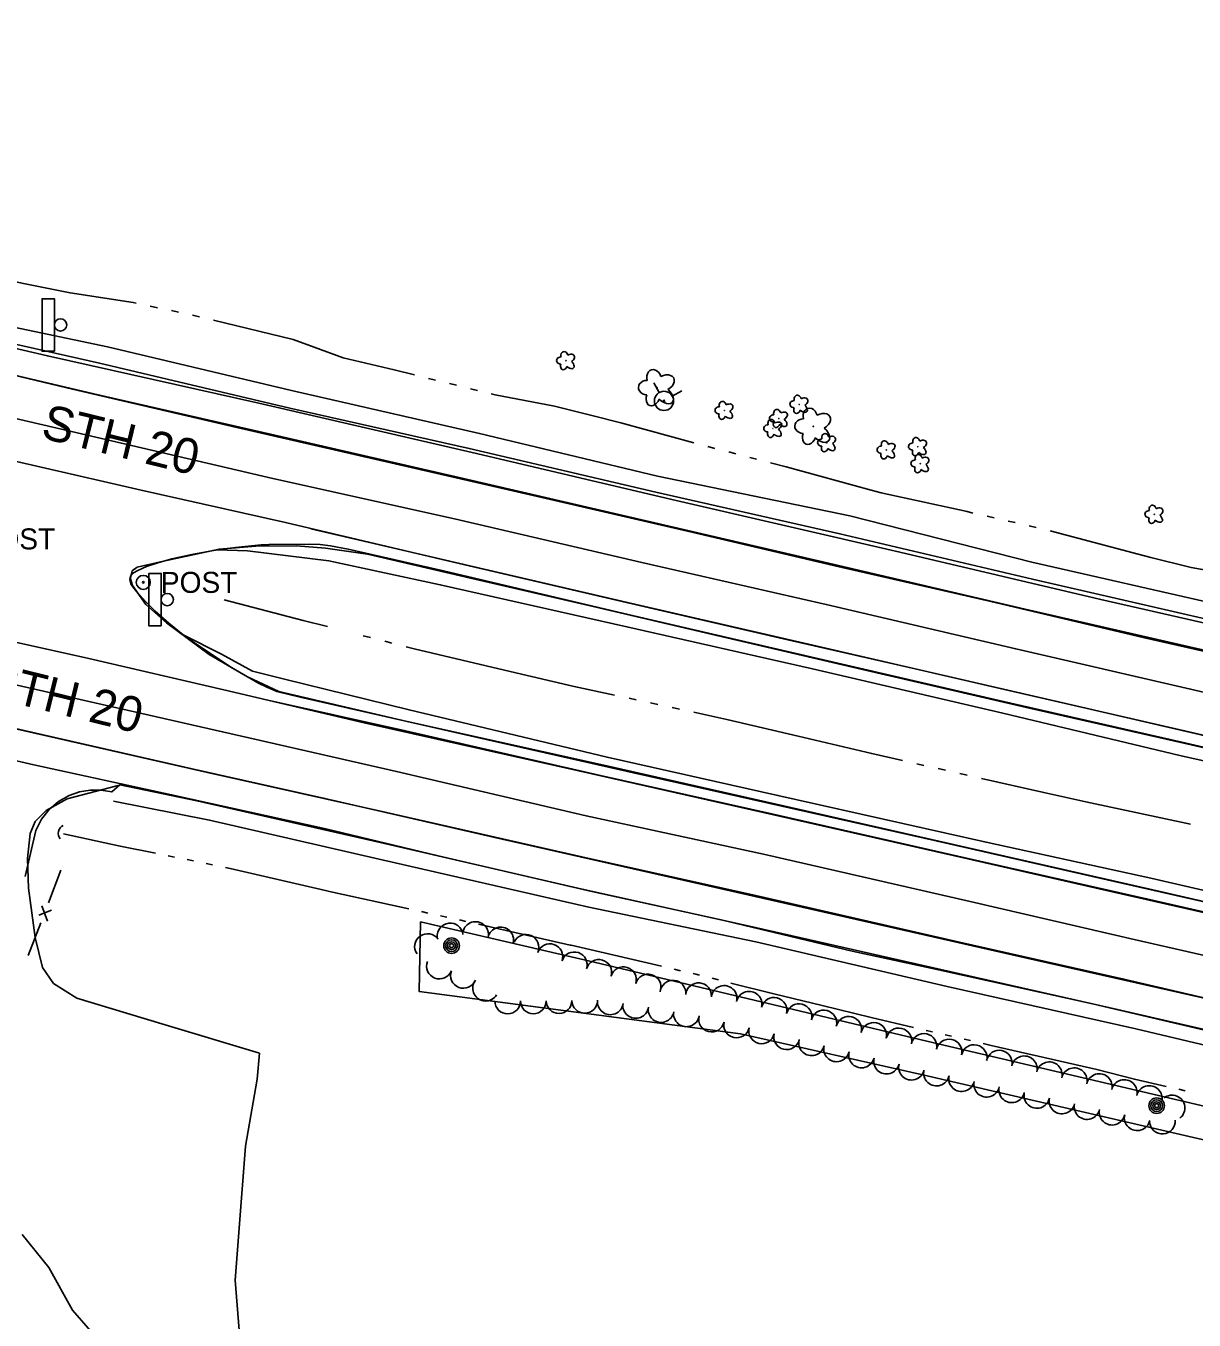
# Model space of a CAD drawing. Extents: x 588843 to 2552415, y 180129 to 269402.
# Drawn here: x 597218.6 to 597551.8, y 184038.8 to 184408.2 of the extents above; entities that cross this region are included whole.
import ezdxf

# ---------------------------------------------------------------- set-up
doc = ezdxf.new("R2010")
doc.units = 0
for name, color, linetype in [('Default', 7, 'Continuous'), ('E_DRN', 7, 'Continuous'), ('E_DWY', 7, 'Continuous'), ('E_FEN_P', 7, 'Continuous'), ('E_LAND_BrushLine', 7, 'Continuous'), ('E_LAND_TreeLine_P', 7, 'Continuous'), ('E_LAND_Vegetation', 7, 'Continuous'), ('E_MISCPROP', 7, 'Continuous'), ('E_RDWY', 7, 'Continuous'), ('E_RDWY_AsphConc', 7, 'Continuous'), ('E_RDWY_Gravel', 7, 'Continuous'), ('E_RDWY_PavtEdge', 7, 'Continuous'), ('E_RDWY_Text', 7, 'Continuous'), ('E_SGN', 7, 'Continuous'), ('E_UTL_WHydrant', 7, 'Continuous'), ('E_WTR_P', 7, 'Continuous')]:
    doc.layers.add(name, color=color, linetype=linetype)

# ---------------------------------------------------------------- blocks, each defined once
blk = doc.blocks.new('BUSH_1')
at = {"layer": 'Default'}
blk.add_circle((0, 0), 0.0916, dxfattribs=at)
for centre, major_axis, ratio in [((-2.84, 0.08), (2.47, -0.06), 0.832022), ((-0.84, 2.66), (0.68, -2.49), 0.782863), ((2.12, 1.37), (-2.64, -1.46), 0.691916), ((-1.15, -2.62), (0.9, 2.43), 0.716896), ((1.86, -1.85), (-2.51, 2.29), 0.560249)]:
    blk.add_ellipse(centre, major_axis=major_axis, ratio=ratio, start_param=1.570796, end_param=4.712389, dxfattribs=at)
blk = doc.blocks.new('DTRE_1_1')
at = {"layer": 'Default'}
blk.add_circle((-0.18, 0), 0.183, dxfattribs=at)
for centre, major_axis, ratio in [((-1.87, 5.32), (1.36, -4.98), 0.782863), ((4.06, 2.74), (-5.27, -2.93), 0.691916), ((-5.87, 0.15), (4.93, -0.12), 0.832022), ((-2.49, -5.24), (1.8, 4.86), 0.716896), ((3.54, -3.71), (-5.01, 4.58), 0.560249)]:
    blk.add_ellipse(centre, major_axis=major_axis, ratio=ratio, start_param=1.570796, end_param=4.712389, dxfattribs=at)
blk = doc.blocks.new('SGN_1')
at = {"layer": 'Default'}
blk.add_lwpolyline([(-3.5, -15), (-10.5, -15), (-10.5, 15), (-3.5, 15)], close=True, dxfattribs=at)
blk.add_circle((0, 0), 3.5, dxfattribs=at)
blk = doc.blocks.new('POST_1')
at = {"layer": 'Default'}
for radius in [4, 0.5]:
    blk.add_circle((0, 0), radius, dxfattribs=at)
blk.add_text('POST', height=12, dxfattribs=at).set_placement((10, -6))
blk = doc.blocks.new('CULV2_4')
at = {"layer": 'E_DRN'}
blk.add_arc((65, 48), 80.7, 216.8699, 323.1301, dxfattribs=at)
blk = doc.blocks.new('HYD_3')
at = {"layer": 'E_UTL_WHydrant'}
for p, q in [((-12.6, 12.6), (-27.3, 27.3)), ((12.6, 12.6), (27.3, 27.3))]:
    blk.add_line(p, q, dxfattribs=at)
for radius in [18, 1.38]:
    blk.add_circle((0, 0), radius, dxfattribs=at)
blk = doc.blocks.new('POLE_3')
at = {"layer": 'E_MISCPROP'}
for radius in [14.6, 11, 7.32, 3.66]:
    blk.add_circle((0, 0), radius, dxfattribs=at)

msp = doc.modelspace()

# ---------------------------------------------------------------- linework, layer by layer
at = {"layer": 'E_DWY'}
for points in [[(597246.35, 184191.76), (597230.31, 184187.57), (597224.35, 184184.27), (597221.18, 184181.15), (597219.79, 184177.65), (597219, 184170.61), (597219.28, 184162.12), (597221.17, 184148.04), (597223.32, 184139.46), (597226.47, 184134.91), (597233.08, 184130.66), (597257.36, 184123.42), (597285.2, 184114.99)], [(597289.65, 183941.21), (597283.81, 184004.99), (597279.81, 184031.22), (597278.24, 184050.27), (597279.4, 184065.09), (597281.23, 184088.44), (597284.53, 184107.61), (597285.2, 184114.99)], [(597217.5, 184063.27), (597225.08, 184053.82), (597231.81, 184041.65), (597240.21, 184032.08), (597248.96, 184023.04), (597253.27, 184015.43), (597252.98, 184008.68), (597247.63, 183979.46), (597243.29, 183967.94), (597236.18, 183952.88), (597231.24, 183945.62), (597225.75, 183938.73), (597219.12, 183923.11), (597199.9, 183923.64)]]:
    msp.add_lwpolyline(points, dxfattribs=at)
at = {"layer": 'E_FEN_P'}
for p, q in [((597225.89, 184155.79), (597222.21, 184154.41)), ((597223.14, 184157.01), (597224.71, 184152.7))]:
    msp.add_line(p, q, dxfattribs=at)
for points in [[(597228.54, 184167.21), (597224.98, 184157.94)], [(597222.79, 184152.2), (597219.24, 184142.93)]]:
    msp.add_lwpolyline(points, dxfattribs=at)
at = {"layer": 'E_LAND_BrushLine'}
for points in [[(597331.09, 184152.51), (597330.77, 184132.6), (597422.37, 184120.57), (597474.79, 184108.77), (597638.69, 184070.76), (597746.75, 184045.7), (597747.75, 184054.95)], [(597747.75, 184054.95), (597638.57, 184080.18), (597475.59, 184118.48), (597380.66, 184140.96), (597331.09, 184152.51)]]:
    msp.add_lwpolyline(points, dxfattribs=at)
at = {"layer": 'E_LAND_TreeLine_P'}
for centre, start, end in [((597339.57, 184148.47), 6.3494, 186.3494), ((597346.83, 184148.87), 347.7278, 167.7278), ((597333.13, 184145.42), 35.0756, 215.0756), ((597354, 184147.31), 347.7278, 167.7278), ((597361.22, 184145.22), 336.4179, 156.4179), ((597368.03, 184142.54), 341.5352, 161.5352), ((597374.99, 184140.22), 341.5352, 161.5352), ((597336.52, 184139.86), 158.7217, 338.7217), ((597381.99, 184138.05), 343.5064, 163.5064), ((597343.35, 184137.2), 158.7217, 338.7217), ((597389.02, 184135.97), 343.5064, 163.5064), ((597396.05, 184133.89), 343.5064, 163.5064), ((597349.69, 184133.56), 148.0436, 328.0436), ((597403.14, 184132.13), 354.556, 174.556), ((597410.44, 184131.43), 354.556, 174.556), ((597417.72, 184130.64), 346.7938, 166.7938), ((597424.86, 184128.97), 346.7938, 166.7938), ((597355.98, 184129.9), 180.3505, 0.3505), ((597363.31, 184129.94), 180.3505, 0.3505), ((597370.64, 184130), 180.6216, 0.6216), ((597377.97, 184130.08), 180.6216, 0.6216), ((597385.27, 184129.66), 171.9341, 351.9341), ((597392.53, 184128.63), 171.9341, 351.9341), ((597431.98, 184127.23), 345.7934, 165.7934), ((597439.09, 184125.43), 345.7934, 165.7934), ((597399.76, 184127.46), 170.4254, 350.4254), ((597406.99, 184126.24), 170.4254, 350.4254), ((597414.16, 184124.73), 166.8205, 346.8205), ((597446.2, 184123.63), 345.7934, 165.7934), ((597453.3, 184121.83), 345.7934, 165.7934), ((597421.3, 184123.06), 166.8205, 346.8205), ((597428.44, 184121.39), 166.8205, 346.8205), ((597460.42, 184120.08), 347.5295, 167.5295), ((597467.58, 184118.5), 347.5295, 167.5295), ((597435.58, 184119.71), 166.8205, 346.8205), ((597442.7, 184117.99), 166.2327, 346.2327), ((597474.74, 184116.92), 347.5295, 167.5295), ((597481.9, 184115.33), 347.5295, 167.5295), ((597449.82, 184116.24), 166.2327, 346.2327), ((597456.94, 184114.5), 166.2327, 346.2327), ((597489.06, 184113.75), 347.5295, 167.5295), ((597496.21, 184112.17), 347.5295, 167.5295), ((597503.37, 184110.55), 346.6039, 166.6039), ((597464.07, 184112.75), 166.2327, 346.2327), ((597471.19, 184111.01), 166.2327, 346.2327), ((597510.5, 184108.85), 346.6039, 166.6039), ((597517.63, 184107.15), 346.6039, 166.6039), ((597478.32, 184109.34), 167.449, 347.449), ((597485.48, 184107.74), 167.449, 347.449), ((597492.64, 184106.15), 167.449, 347.449), ((597524.76, 184105.46), 346.6039, 166.6039), ((597531.89, 184103.76), 346.6039, 166.6039), ((597499.79, 184104.56), 167.449, 347.449), ((597506.95, 184102.96), 167.449, 347.449), ((597539.02, 184102.06), 346.6039, 166.6039), ((597545.51, 184099.35), 308.2942, 128.2942), ((597514.11, 184101.37), 167.449, 347.449), ((597521.26, 184099.78), 167.449, 347.449), ((597528.42, 184098.18), 167.449, 347.449), ((597535.57, 184096.59), 167.449, 347.449), ((597542.78, 184095.63), 183.8381, 3.8381)]:
    msp.add_arc(centre, 3.67, start, end, dxfattribs=at)
at = {"layer": 'E_RDWY'}
for points in [[(596831.75, 184400.44), (596858.75, 184393.38), (596892.45, 184384.48), (596919.43, 184377.87), (596951.34, 184370.1), (596983.45, 184362.27), (597016.79, 184354.74), (597046.68, 184347.63), (597079.81, 184340.05), (597123.33, 184329.81), (597158.41, 184321.69), (597191.53, 184314.11), (597231.88, 184304.53), (597278.69, 184293.59), (597318.11, 184284.48), (597364.49, 184273.87), (597407.26, 184263.94), (597449.32, 184254.1), (597493.42, 184244.01), (597537.64, 184233.58), (597587.58, 184222.19), (597639.5, 184210.36), (597689.48, 184198.75)], [(596815.1, 184380.55), (596855.37, 184370.13), (596904.64, 184357.46), (596969.32, 184341.58), (597021.23, 184329.33), (597056.25, 184321.02), (597109.12, 184308.82), (597158.76, 184297.1), (597205.08, 184286.29), (597251.45, 184275.68), (597292.62, 184266.4), (597342.16, 184254.71), (597389.87, 184243.62), (597437.19, 184232.64), (597472.2, 184224.65), (597520.55, 184213.6), (597569.33, 184202.21), (597631.03, 184188.1), (597685.98, 184175.44)], [(596807.31, 184329.2), (596842.23, 184319.94), (596876.16, 184311.09), (596912.83, 184301.9), (596945.36, 184294.06), (596984.2, 184285.11), (597027.27, 184275.1), (597066.2, 184266.12), (597109.25, 184256.43), (597150.88, 184246.92), (597194.98, 184236.83), (597236.5, 184227.67), (597275.02, 184218.71), (597315.1, 184209.31), (597376.66, 184195.45), (597431.4, 184183.15), (597485.2, 184170.91), (597526.83, 184161.4), (597571.25, 184151.33), (597617.09, 184141.08), (597657, 184131.83), (597684.02, 184125.73)], [(596813.68, 184302.57), (596852.3, 184292.45), (596895.32, 184281.51), (596939.25, 184270.83), (596989.1, 184259.47), (597040.33, 184247.83), (597085.56, 184237.65), (597127.55, 184227.93), (597167.69, 184218.73), (597214.72, 184207.83), (597265.96, 184196.19), (597303.87, 184187.71), (597352.3, 184176.53), (597403.95, 184164.88), (597455.48, 184153.16), (597504.06, 184142.15), (597550.85, 184131.53), (597599.74, 184120.53), (597645.79, 184109.91), (597674, 184103.58)]]:
    msp.add_lwpolyline(points, dxfattribs=at)
at = {"layer": 'E_RDWY_AsphConc'}
for points in [[(597033.85, 184359.31), (597089.33, 184346.21), (597137.85, 184335.37), (597192.7, 184322.52), (597239.53, 184311.9), (597293.86, 184299.11)], [(597293.86, 184299.11), (597345.02, 184287.61), (597398.23, 184275.12), (597450.79, 184263.24), (597505.69, 184250.3), (597555.33, 184238.87), (597609.7, 184226.42), (597658.86, 184214.84), (597713.09, 184202.83), (597763.94, 184190.68), (597815.6, 184178.73)], [(597290.73, 184218.21), (597281.78, 184222.37), (597281.78, 184222.37), (597277, 184225.13), (597277, 184225.13), (597266.65, 184232.06), (597266.65, 184232.06), (597263.42, 184234.4), (597263.42, 184234.4), (597259.36, 184237.68), (597255.45, 184241.14), (597255.45, 184241.14), (597252.74, 184243.82), (597250.2, 184246.66), (597250.2, 184246.66), (597249.06, 184248.13), (597249.06, 184248.13), (597248.54, 184248.96), (597248.54, 184248.96), (597248.19, 184250.19), (597248.19, 184250.19), (597248.39, 184251.09), (597248.39, 184251.09), (597249.01, 184251.86), (597249.01, 184251.86), (597250.12, 184252.6), (597250.12, 184252.6), (597251.73, 184253.35), (597251.73, 184253.35), (597252.96, 184253.85), (597252.96, 184253.85), (597256.19, 184254.92), (597256.19, 184254.92), (597260.21, 184256.05), (597260.21, 184256.05), (597265.91, 184257.35), (597265.91, 184257.35), (597273.08, 184258.63), (597273.08, 184258.63), (597278.37, 184259.34), (597278.37, 184259.34), (597285.68, 184260.06), (597285.68, 184260.06), (597287.94, 184260.17), (597287.94, 184260.17), (597299.44, 184260.25), (597299.44, 184260.25), (597302.46, 184260.13), (597305.46, 184259.76), (597305.46, 184259.76), (597310.51, 184258.82), (597315.52, 184257.65), (597315.52, 184257.65), (597337.67, 184252.68), (597390.76, 184240.14), (597443.59, 184227.82), (597497.47, 184215.36), (597548.28, 184203.73), (597601.08, 184191.58)], [(597290.73, 184218.21), (597327.3, 184209.7), (597383.38, 184197.18), (597432.57, 184186.07), (597491.58, 184172.68), (597538.82, 184161.9), (597594.29, 184149.17), (597642.79, 184138.28), (597693.87, 184126.73), (597748.61, 184114.32), (597798.34, 184103.09)], [(597218.33, 184165.44), (597221.43, 184178.6), (597223.03, 184181.75), (597225.2, 184184.53), (597227.87, 184186.83), (597230.94, 184188.58), (597230.94, 184188.58), (597233.86, 184189.59), (597236.91, 184190.1), (597240, 184190.08), (597243.04, 184189.54), (597243.04, 184189.54), (597245.38, 184191.57), (597267.32, 184186.99), (597319.66, 184175.1), (597377.22, 184161.77), (597424.09, 184151.43), (597482.49, 184138.26), (597529.91, 184127.44), (597583.69, 184115.08), (597633.56, 184103.88), (597686.64, 184091.77), (597740.17, 184080.36), (597789.27, 184068.6)]]:
    msp.add_lwpolyline(points, dxfattribs=at)
at = {"layer": 'E_RDWY_Gravel'}
for points in [[(596831.79, 184408.16), (596876.04, 184396.59), (596912.48, 184387.35), (596960.41, 184375.89), (597008.48, 184364.6), (597059.68, 184352.45), (597113.53, 184339.98), (597173.17, 184326.02), (597224.72, 184313.98), (597285, 184300.47), (597347.07, 184286.15), (597402.84, 184273.05), (597467.86, 184258.02), (597525.2, 184244.48), (597582.05, 184231.5), (597632.68, 184219.92), (597677.17, 184209.73), (597698.04, 184205.01)], [(597190.57, 184327.28), (597241.84, 184316.54), (597294.28, 184304.14), (597348, 184291.83), (597398.75, 184279.68), (597453.57, 184268.37), (597505.54, 184255.11), (597559.03, 184242.96), (597609.02, 184232.06), (597662.1, 184219.26), (597715.37, 184207.09), (597765.01, 184195.24), (597817.99, 184183.71), (597867.41, 184172.44), (597918.85, 184159.91), (597970.49, 184147.94), (598019.64, 184136.8), (598071.14, 184124.64), (598124.58, 184111.68), (598180.31, 184099.55), (598221.02, 184089.9), (598272.49, 184077.54)], [(596809.86, 184294.62), (596850.9, 184283.59), (596897.3, 184272.34), (596947.42, 184260.06), (596997.62, 184248.5), (597042.38, 184238.12), (597083.63, 184229.14), (597131.86, 184218.02), (597177.46, 184207.3), (597220.85, 184197.3), (597260.12, 184188.76), (597304.1, 184179.02), (597336.14, 184171.32), (597380.02, 184161.19), (597416.89, 184153.1), (597454.25, 184144.14), (597478.85, 184138.81), (597522.83, 184129.07), (597564.61, 184119.31), (597606.68, 184109.89), (597645.27, 184100.8), (597671.8, 184094.83)], [(597252.73, 184243.05), (597248.98, 184248.5), (597248.44, 184250.34), (597248.54, 184251.15), (597248.86, 184252.64), (597250.32, 184253.71), (597257.83, 184255.41), (597273.7, 184258.81), (597284.14, 184259.71), (597295.72, 184259.76), (597304.07, 184259.14), (597316, 184257.42), (597345.42, 184250.55), (597380.4, 184242.45), (597415.65, 184234.18), (597457.22, 184224.48), (597505.25, 184213.41), (597550.94, 184202.99), (597596.21, 184192.58), (597641.68, 184182.11), (597685.38, 184172.13)], [(597273.08, 184258.63), (597281.75, 184258.4), (597304.97, 184255.53), (597336.77, 184248.69), (597390.03, 184236.69), (597442.94, 184224.67), (597497.2, 184212.03), (597547.7, 184199.99), (597600.61, 184188.16), (597651.77, 184176.09), (597703.59, 184163.69), (597756.64, 184152.36), (597806.99, 184141.09)], [(597252.73, 184243.05), (597258.65, 184237.84), (597270.87, 184228.79), (597284.7, 184220.65), (597287.5, 184219.36), (597287.6, 184219.33), (597290.12, 184218.21), (597296.82, 184216.57), (597349.45, 184204.65), (597391.89, 184195.02), (597434.16, 184185.54), (597478.58, 184175.47), (597524.88, 184164.99), (597575.63, 184153.48), (597617.16, 184144), (597660.28, 184134.18), (597683.63, 184128.88)], [(597263.42, 184234.4), (597274.34, 184228.9), (597283.21, 184224.06), (597292.33, 184221.71), (597327.85, 184212.94), (597384.37, 184199.45), (597433.08, 184188.56), (597492.47, 184175.21), (597539.44, 184164.91), (597595.44, 184151.99), (597643.5, 184140.76), (597694.55, 184128.82), (597748.96, 184116.6), (597800.36, 184106.09)], [(597243.57, 184186.93), (597270.95, 184181.53), (597319.38, 184170.33), (597379.19, 184156.69), (597426.74, 184146.77), (597481.4, 184134), (597535.22, 184121.95), (597584.91, 184110.19), (597641.96, 184097.26), (597688.18, 184086.7), (597741, 184075.58), (597788.42, 184063.44), (597841.99, 184052.04), (597890.44, 184041.33), (597943.81, 184029.04), (597994.52, 184016.98), (598050.96, 184004.74), (598096.96, 183994.09), (598150.56, 183982.43), (598196.66, 183971.94), (598248.65, 183960.47)]]:
    msp.add_lwpolyline(points, dxfattribs=at)
at = {"layer": 'E_RDWY_PavtEdge'}
for points in [[(597032.52, 184351.1), (597087.15, 184338.3), (597136.04, 184327.06), (597191.78, 184314.01), (597237.97, 184303.12), (597291.62, 184290.88)], [(597029.63, 184339.65), (597083.89, 184326.77), (597134.37, 184315.21), (597188.15, 184302.49), (597235.61, 184291.45), (597289.03, 184278.99)], [(597291.62, 184290.88), (597343.38, 184279.02), (597396.75, 184266.64), (597448.76, 184254.59), (597503.58, 184241.71), (597553.83, 184230.24), (597607.26, 184217.93), (597657.71, 184205.72), (597710.88, 184194.54), (597762.17, 184180.69), (597813.54, 184170.18)], [(597289.03, 184278.99), (597340.84, 184267.49), (597394.28, 184255.02), (597446.89, 184243.07), (597500.94, 184230.36), (597550.82, 184218.93), (597604.41, 184206.46), (597655.77, 184194.61), (597708.5, 184183.04), (597759.86, 184170.47), (597810.86, 184158.52)], [(597010.03, 184267.11), (597066.57, 184254.1), (597111.43, 184243.82), (597172.16, 184229.93), (597215.21, 184220.25), (597274.65, 184206.74), (597324.3, 184195.36), (597378.35, 184182.75), (597428.94, 184171.77), (597487.92, 184158.32), (597534.75, 184147.43), (597590.22, 184134.82), (597637.98, 184124.12), (597690.95, 184112.09), (597744.11, 184100.06), (597794.65, 184088.57)], [(597299.85, 184264.6), (597338.23, 184255.74), (597391.43, 184243.32), (597444.26, 184231.18), (597497.71, 184218.79), (597549.08, 184207.03), (597601.95, 184194.82), (597653.62, 184183.09), (597705.01, 184170.95), (597757.84, 184158.81), (597808.55, 184147.03)], [(597011.19, 184254.44), (597064.53, 184242.11), (597113.42, 184230.99), (597170.53, 184218.13), (597211.89, 184208.42), (597270.4, 184195.06), (597321.47, 184183.71)], [(597287.62, 184215.77), (597326.82, 184207.03), (597382.44, 184194.23), (597431.73, 184183.17), (597490.73, 184169.79), (597538.23, 184159.07), (597593.7, 184146.38), (597641.97, 184135.53), (597693.3, 184123.88), (597747.97, 184111.45), (597797.71, 184100.24)], [(597321.47, 184183.71), (597379.26, 184170.55), (597425.91, 184160.18), (597484.92, 184146.64), (597531.8, 184136.16), (597586.8, 184123.32), (597635.19, 184112.5), (597688.79, 184100.43), (597741.63, 184088.53), (597791.51, 184077)]]:
    msp.add_lwpolyline(points, dxfattribs=at)
at = {"layer": 'E_WTR_P'}
for points in [[(597191.56, 184339.99), (597220.72, 184334.08)], [(597220.73, 184334.08), (597231.17, 184331.96), (597249.12, 184329.2), (597250.03, 184329.01)], [(597254.05, 184328.17), (597256.06, 184327.75)], [(597260.07, 184326.9), (597262.08, 184326.48)], [(597266.1, 184325.64), (597266.51, 184325.55), (597268.1, 184325.17)], [(597272.08, 184324.2), (597294.78, 184318.69), (597300.79, 184316.49)], [(597300.79, 184316.49), (597309.1, 184313.46), (597323.59, 184309.98), (597329.42, 184308.54)], [(597333.4, 184307.56), (597335.4, 184307.07)], [(597339.38, 184306.08), (597341.37, 184305.59)], [(597345.35, 184304.6), (597347.35, 184304.11)], [(597351.33, 184303.13), (597352.43, 184302.85), (597369.31, 184299.66), (597380.4, 184296.84)], [(597380.4, 184296.84), (597388.27, 184294.84), (597409.14, 184289.17)], [(597413.11, 184288.11), (597415.1, 184287.6)], [(597419.07, 184286.57), (597421.06, 184286.05)], [(597425.03, 184285.02), (597427.01, 184284.51)], [(597430.99, 184283.48), (597435.48, 184282.32), (597459.71, 184275.71)], [(597459.71, 184275.71), (597462.56, 184274.94), (597487.03, 184269.54), (597488.73, 184269.15)], [(597492.73, 184268.24), (597494.73, 184267.78)], [(597498.73, 184266.87), (597500.73, 184266.42)], [(597504.73, 184265.51), (597506.73, 184265.05)], [(597510.72, 184264.07), (597535.82, 184257.42), (597539.49, 184256.5)], [(597539.49, 184256.5), (597550.97, 184253.65), (597568.6, 184250.42)], [(597275.07, 184244.34), (597297.64, 184238.52), (597304.62, 184236.73)], [(597314.81, 184234.12), (597316.85, 184233.6)], [(597320.93, 184232.55), (597322.97, 184232.03)], [(597327.04, 184230.98), (597329.35, 184230.39), (597356.74, 184223.95)], [(597356.74, 184223.95), (597374.95, 184219.68), (597386.49, 184217.18)], [(597390.61, 184216.29), (597392.66, 184215.85)], [(597396.78, 184214.96), (597398.83, 184214.52)], [(597402.95, 184213.63), (597405.01, 184213.18)], [(597409.12, 184212.29), (597418.5, 184210.27), (597438.86, 184205.47)], [(597438.86, 184205.47), (597459.86, 184200.52), (597468.58, 184198.54)], [(597472.68, 184197.6), (597474.74, 184197.14)], [(597478.84, 184196.2), (597480.89, 184195.74)], [(597485, 184194.81), (597487.05, 184194.34)], [(597491.15, 184193.41), (597508.92, 184189.37), (597520.94, 184186.78)], [(597520.94, 184186.78), (597550.77, 184180.36)], [(597229.29, 184177.63), (597245.45, 184174.11), (597255.52, 184172.06)], [(597259.14, 184171.33), (597260.96, 184170.96)], [(597264.58, 184170.23), (597266.39, 184169.86)], [(597270.02, 184169.13), (597271.83, 184168.76)], [(597275.46, 184168.02), (597276.81, 184167.75), (597301.58, 184161.97)], [(597301.58, 184161.97), (597306.04, 184160.93), (597327.77, 184156.19)], [(597331.38, 184155.4), (597333.19, 184155)], [(597336.8, 184154.21), (597338.61, 184153.82)], [(597342.22, 184153.03), (597344.03, 184152.63)], [(597347.63, 184151.81), (597373.78, 184145.87)], [(597373.78, 184145.87), (597374.08, 184145.8), (597399.91, 184139.81)], [(597403.51, 184138.97), (597405.31, 184138.55)], [(597408.92, 184137.72), (597409.64, 184137.55), (597410.71, 184137.28)], [(597414.3, 184136.37), (597416.09, 184135.92)], [(597419.68, 184135.01), (597431.96, 184131.91), (597445.71, 184128.58)], [(597445.71, 184128.58), (597459.64, 184125.2), (597471.8, 184122.36)], [(597475.4, 184121.52), (597477.2, 184121.1)], [(597480.8, 184120.26), (597482.6, 184119.84)], [(597486.2, 184119), (597488.01, 184118.58)], [(597491.61, 184117.74), (597493.91, 184117.2), (597517.75, 184111.77)], [(597517.75, 184111.77), (597524.07, 184110.33), (597534.77, 184107.59), (597543.83, 184105.53)], [(597547.43, 184104.71), (597549.24, 184104.3)]]:
    msp.add_lwpolyline(points, dxfattribs=at)

# ---------------------------------------------------------------- block references
at = {"layer": 'E_DRN', "xscale": 0.029857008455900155, "yscale": 0.029857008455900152, "rotation": -102.4392018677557}
msp.add_blockref('CULV2_4', (597229.21, 184179.96), dxfattribs=at)
at = {"layer": 'E_LAND_Vegetation', "xscale": 0.5, "yscale": 0.5}
for name, p in [('BUSH_1', (597372.62, 184312.61)), ('DTRE_1_1', (597398.68, 184304.87)), ('BUSH_1', (597439.16, 184300.16)), ('BUSH_1', (597417.8, 184298.42)), ('BUSH_1', (597433.32, 184296.11)), ('DTRE_1_1', (597443.27, 184293.86)), ('BUSH_1', (597431.69, 184293.27)), ('BUSH_1', (597447.05, 184289.21)), ('BUSH_1', (597464.02, 184287.15)), ('BUSH_1', (597472.99, 184288.08)), ('BUSH_1', (597473.68, 184283.23)), ('BUSH_1', (597540.44, 184268.77))]:
    msp.add_blockref(name, p, dxfattribs=at)
at = {"layer": 'E_MISCPROP', "xscale": 0.5, "yscale": 0.5}
for p in [(597200.08, 184261.76), (597252.05, 184249.36)]:
    msp.add_blockref('POST_1', p, dxfattribs=at)
at = {"layer": 'E_MISCPROP', "xscale": 0.1524003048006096, "yscale": 0.15240030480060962, "rotation": -15.451989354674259}
for p in [(597339.98, 184145.69), (597541.13, 184100.03)]:
    msp.add_blockref('POLE_3', p, dxfattribs=at)
at = {"layer": 'E_SGN', "xscale": 0.5, "yscale": 0.5}
for p in [(597228.44, 184322.81), (597258.9, 184244.43)]:
    msp.add_blockref('SGN_1', p, dxfattribs=at)
at = {"layer": 'E_UTL_WHydrant', "xscale": 0.1524003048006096, "yscale": 0.15240030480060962, "rotation": -15.451989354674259}
msp.add_blockref('HYD_3', (597400.58, 184301.15), dxfattribs=at)

# ---------------------------------------------------------------- texts
at = {"layer": 'E_RDWY_Text'}
for p in [(597222.5, 184290.65), (597206.41, 184217.02)]:
    msp.add_text('STH 20', height=10, rotation=346.2176, dxfattribs=at).set_placement(p)

doc.saveas('drawing.dxf')
